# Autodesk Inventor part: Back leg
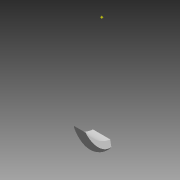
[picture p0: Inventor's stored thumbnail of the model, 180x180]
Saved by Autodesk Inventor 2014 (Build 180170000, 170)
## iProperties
Created: 2013-09
Part Number: Back leg
Material: Generic
Document SubType Name: Modeling
Designer: Joey Mason
Appearance: Reflective - White
Mass: 1001.7 g
Surface Area: 2819.14 cm^2
Volume: 1001.7 cm^3
Density: 1 g/cm^3
Author: Joey Mason
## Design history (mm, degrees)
sketch "Sketch1"
  geometry: L1 (-1045.953, 551.745)-(799.079, 551.745); L2 (799.079, 551.745)-(799.079, -678.891); L3 (799.079, -678.891)-(-1045.953, -678.891); L4 (-1045.953, -678.891)-(-1045.953, 551.745); 4 further points; 1 other entity
  constraints: 1 vertical, 6 other
  node "Image1"
sketch "Sketch6"
  geometry: 5 further points; 1 other entity
  constraints: 1 coincident, 4 other
sketch "Sketch7"
  geometry: 4 further points; 1 other entity
  constraints: 1 coincident, 4 other
sketch "Sketch8"
  geometry: 4 further points; 1 other entity
  constraints: 4 other
sketch "Sketch9"
  geometry: 5 further points; 1 other entity
  constraints: 1 coincident, 2 other
workpoint "Work Point5"
loft "Loft2" dims "d70" = 0, "d71" = 90 deg, "d72" = 0, "d73" = 90 deg, "d74" = 0, "d75" = 90 deg, "d76" = 0, "d77" = 90 deg, "d78" = 0, "d79" = 90 deg, "d80" = 0, "d81" = 90 deg, "d82" = 0, "d83" = 90 deg
workplane "Work Plane1"
sketch "Sketch10"
  geometry: L1 (0, 0)-(0.002, -165.1); L2 (-72.009, 197.105)-(-42.932, 117.215); L3 (-29.628, -144.286)-(-47.688, -246.71); L4 (-47.688, -246.71)-(-267.69, 18.133); L5 (-267.69, 18.133)-(-72.009, 197.105); L6 (267.69, 18.139)-(72.005, 197.107); L7 (72.005, 197.107)-(42.929, 117.216); L8 (47.694, -246.709)-(267.69, 18.139); L9 (29.631, -144.286)-(47.694, -246.709); L10 (-72.009, 197.105)-(-78.879, 319.237); L11 (-78.879, 319.237)-(96.407, 329.096); L12 (96.407, 329.096)-(72.977, 196.217); L13 (29.631, -144.286)-(47.694, -246.709); 4 further points; 3 other entities
  constraints: 26 end point, 5 symmetric about line, 3 coincident, 1 collinear, 1 parallel, 1 perpendicular, 1 point on line, 16 other
extrude "Extrusion5" cut sketch "Sketch10" distance "d111" = 279.4; taper "d112" = 0 deg
sketch "Sketch14"
  geometry: L1 (0, 0)-(-369.02, 0); L2 (-369.02, 0)-(-369.02, -183.383); L3 (-369.02, -183.383)-(0, -183.383); L4 (0, -183.383)-(0, 0)
  constraints: 8 end point, 2 parallel, 1 horizontal, 1 perpendicular
extrude "Extrusion6" cut sketch "Sketch14" stored distance "d113" = 279.4; taper "d114" = 0 deg
workplane "Work Plane2"
workplane "Work Plane3"
sketch "Sketch16"
  geometry: L1 (48.491, 34.064)-(0, 0); 2 further points; 1 other entity
  constraints: 2 end point, 2 other
extrude "Extrusion7" join sketch "Sketch16" distance "d115" = 127; taper "d116" = 0 deg
sketch "Sketch17"
  geometry: L1 (-165.1, 106.554)-(-173.055, 130.917); L2 (-173.055, 130.917)-(-134.733, 130.917); L3 (-134.733, 130.917)-(-144.286, 106.104); L4 (-165.1, 106.554)-(-144.286, 106.104); 1 further point
  constraints: 8 end point, 1 horizontal, 1 other
extrude "Extrusion8" cut sketch "Sketch17" stored distance "d117" = 127; taper "d118" = 0 deg
sketch "Sketch18"
  geometry: L1 (0, 0)-(59.259, 0) reference; L2 (59.259, 0)-(59.259, 106.104) reference; L3 (0, 106.104)-(59.259, 106.104) reference; L4 (0, 0)-(0, 106.104) reference; 1 further point
extrude "Extrusion9" join sketch "Sketch18" distance "d119" = 5.08; taper "d120" = 0 deg
sketch "Sketch19"
  geometry: L1 (106.104, -103.998)-(106.104, 0) reference; L2 (0, 0)-(106.104, 0) reference; L3 (0, 0)-(-4.488, 9.849); 1 further point
  constraints: 2 end point, 1 other
sketch "Sketch20"
  geometry: L1 (29.631, -144.286)-(27.921, -134.587) reference; L2 (28.502, -137.88)-(32.223, -137.555); L3 (32.223, -137.555)-(29.631, -144.286); 1 further point
  constraints: 4 end point, 1 point on line
extrude "Extrusion10" cut sketch "Sketch20" distance "d121" = 279.4; taper "d122" = 0 deg
sketch "Sketch21"
  geometry: L1 (106.104, -0.003)-(106.104, 0) reference; L2 (106.104, 0)-(0, 0) reference; L3 (0, 0)-(0, -104.004) reference; L4 (106.104, 0)-(112.153, 12.957); 1 further point
  constraints: 2 end point, 1 other
sketch "Sketch22"
  geometry: L1 (-29.628, -144.286)-(-27.378, -131.526) reference; L2 (-29.628, -144.286)-(-36.3, -132.786); L3 (-36.3, -132.786)-(-27.378, -131.526); 1 further point
  constraints: 4 end point
extrude "Extrusion11" cut sketch "Sketch22" distance "d123" = 279.4; taper "d124" = 0 deg
sketch "Sketch23"
  geometry: L1 (-165.1, 106.554)-(-134.627, 105.895); L2 (-134.627, 105.895)-(-135.664, 107.432); L3 (-135.664, 107.432)-(-165.1, 106.554); 2 further points
  constraints: 6 end point, 1 other
  dimensions: "d125" = 30.48 distance of L1.start L1.end
extrude "Extrusion12" cut sketch "Sketch23" stored distance "d126" = 279.4; taper "d127" = 0 deg
sketch "Sketch24"
  geometry: L1 (-139.206, 105.994)-(-139.206, 0) reference; L2 (-139.206, 105.994)-(-141.746, 105.994); L3 (-139.206, 105.994)-(-141.746, 105.994); L4 (-141.746, 105.994)-(-141.746, -3.05); L5 (-141.746, -3.05)-(-139.206, -3.05); L6 (-139.206, -3.05)-(-139.206, 105.994); L7 (-141.746, 105.994)-(-141.746, 117.821); L8 (-141.746, 117.821)-(-139.206, 105.994); 1 further point
  constraints: 14 end point, 3 parallel, 2 perpendicular, 1 horizontal
  dimensions: "d128" = 2.54 distance of L1.start L2.end
extrude "Extrusion13" cut sketch "Sketch24" stored distance "d129" = 279.4; taper "d130" = 0 deg
sketch "Sketch25"
  geometry: L1 (-141.746, 0)-(-141.746, 106.049) reference; L2 (-246.704, 0)-(-141.746, 0) reference; L3 (-246.704, 0)-(-216.224, 0); L4 (-246.704, 0)-(-223.844, 0); 2 further points
  constraints: 4 end point, 2 point on line, 3 other
  dimensions: "d131" = 30.48 distance of L2.start L3.end; "d134" = 22.86 distance of L2.start L4.end
extrude "Extrusion15" cut sketch "Sketch25" stored distance "d135" = 279.4; taper "d136" = 0 deg
body "Solid2"
other parameters: "d85" = 132.08
